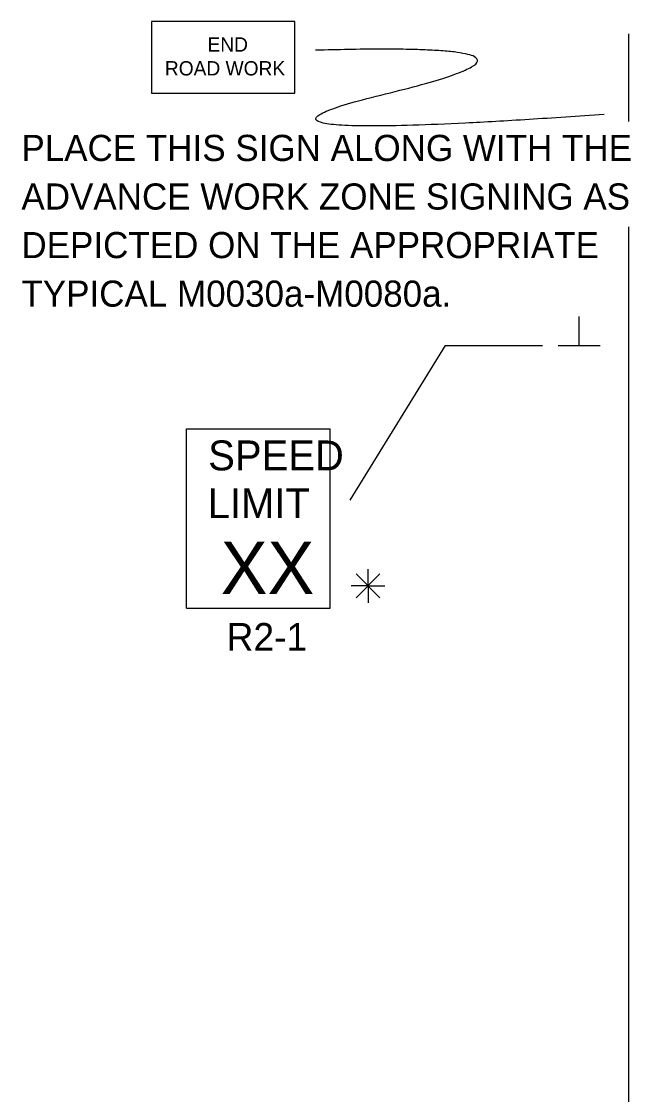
# Model space of a CAD drawing. Extents: x 16734 to 18475, y 5704 to 7011.
# Drawn here: x 16733.5 to 16896.4, y 6636.8 to 6924.1 of the extents above; entities that cross this region are included whole.
import ezdxf

# ---------------------------------------------------------------- set-up
doc = ezdxf.new("R2010")
doc.units = 0
for name, color, linetype in [('PAVT_EDGE_EX', 7, 'Continuous'), ('TRAFFIC_SIGNS_PR', 7, 'Continuous'), ('TYPICAL_TEXT_DIMEN_PR', 7, 'Continuous')]:
    doc.layers.add(name, color=color, linetype=linetype)

msp = doc.modelspace()

# ---------------------------------------------------------------- linework, layer by layer
at = {"layer": 'PAVT_EDGE_EX'}
for p, q in [((16895.85, 6920.73), (16895.85, 6897.26)), ((16895.85, 6869.12), (16895.85, 6024.13))]:
    msp.add_line(p, q, dxfattribs=at)
at = {"layer": 'TRAFFIC_SIGNS_PR'}
for p, q in [((16777.71, 6815.04), (16816.11, 6815.04)), ((16777.71, 6767.04), (16777.71, 6815.04)), ((16816.11, 6767.04), (16816.11, 6815.04)), ((16777.71, 6767.04), (16816.11, 6767.04))]:
    msp.add_line(p, q, dxfattribs=at)
msp.add_lwpolyline([(16768.29, 6904.86), (16806.69, 6904.86), (16806.69, 6924.06), (16768.29, 6924.06)], close=True, dxfattribs=at)
msp.add_open_spline([(16889.36, 6899.17), (16774.14, 6890.93), (16888.05, 6918.52), (16812.21, 6916.35)], degree=2, dxfattribs=at)
at = {"layer": 'TYPICAL_TEXT_DIMEN_PR'}
for p, q in [((16882.73, 6837.3), (16882.73, 6845.08)), ((16846.85, 6837.3), (16821.33, 6795.95)), ((16846.85, 6837.3), (16872.85, 6837.3)), ((16877.1, 6837.3), (16888.35, 6837.3)), ((16829.41, 6776.18), (16823.03, 6769.8)), ((16823.04, 6776.18), (16829.41, 6769.8)), ((16826.22, 6772.99), (16826.22, 6777.45)), ((16826.22, 6772.99), (16821.69, 6772.99)), ((16826.22, 6772.99), (16829.41, 6772.99)), ((16826.22, 6772.99), (16830.7, 6772.99)), ((16826.22, 6772.99), (16826.22, 6768.49))]:
    msp.add_line(p, q, dxfattribs=at)

# ---------------------------------------------------------------- texts
at = {"layer": 'TRAFFIC_SIGNS_PR'}
for s, height, p in [('END', 3.831, (16783.29, 6915.99)), ('ROAD WORK', 3.831, (16771.9, 6909.61)), ('PLACE THIS SIGN ALONG WITH THE', 7, (16733.52, 6886.71)), ('ADVANCE WORK ZONE SIGNING AS', 7, (16733.52, 6873.71)), ('DEPICTED ON THE APPROPRIATE', 7, (16733.52, 6860.71)), ('TYPICAL M0030a-M0080a.', 7, (16733.52, 6847.71)), ('SPEED', 8, (16783.48, 6803.91)), ('LIMIT', 8, (16783.32, 6791.11)), ('XX', 14.031, (16786.83, 6770.8)), ('R2-1', 7.44, (16788.39, 6755.6))]:
    msp.add_text(s, height=height, dxfattribs=at).set_placement(p)

doc.saveas('drawing.dxf')
